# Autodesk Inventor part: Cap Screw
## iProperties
Shininess: 77.0
Length Units: 11269
Angle Units: 11279
Time Units: 11290
Mass Units: 11283
Length Display Precision: 3
Angle Display Precision: 2
Created: 2002-02
Part Number: Cap Screw
Document SubType Name: Modeling
Designer: ***
Density: 0.0
Volumn: 0.0
Area: 0.0
PropertySet Name: Model Information
Control State: 0
Master: False
Checked Out: False
Author: ***
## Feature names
1. Revolution1
2. Extrusion1
3. Extrusion2
